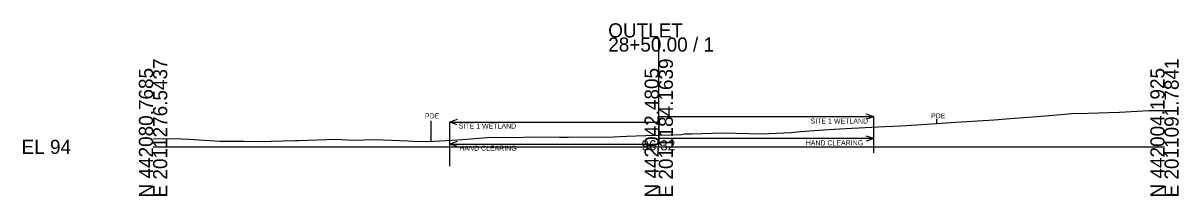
# Model space of a CAD drawing. Extents: x -26 to 1203, y -15 to 9526.
# Drawn here: x 974.3 to 1202.8, y 8490.3 to 8524.5 of the extents above; entities that cross this region are included whole.
import ezdxf

# ---------------------------------------------------------------- set-up
doc = ezdxf.new("R2010")
doc.units = 0
for name, color, linetype in [('Exist Cross Section Cell', 7, 'Continuous'), ('Exist XS Center Line Elevation Label', 7, 'Continuous'), ('Exist XS Ground Line', 7, 'Continuous'), ('Scratch_Level_0', 7, 'Continuous')]:
    doc.layers.add(name, color=color, linetype=linetype)

msp = doc.modelspace()

# ---------------------------------------------------------------- linework, layer by layer
at = {"layer": 'Exist Cross Section Cell'}
for p, q in [((1100, 8500), (1100, 8521.64)), ((1000, 8500), (1100, 8500)), ((1100, 8500), (1200, 8500))]:
    msp.add_line(p, q, dxfattribs=at)
at = {"layer": 'Exist XS Ground Line'}
msp.add_lwpolyline([(1000, 8501.57), (1002.01, 8501.66), (1005.6, 8501.56), (1007.08, 8501.51), (1013.25, 8501.1), (1017.91, 8501.13), (1020.9, 8501.04), (1028.12, 8501.23), (1028.73, 8501.26), (1036.21, 8501.55), (1039.56, 8501.36), (1043.86, 8501.43), (1050.38, 8501.17), (1051.51, 8501.14), (1054.24, 8501.07), (1059.17, 8501.32), (1061.21, 8501.49), (1066.82, 8501.95), (1072.03, 8501.86), (1074.47, 8501.99), (1080.36, 8501.93), (1082.13, 8501.95), (1082.86, 8501.97), (1089.78, 8501.94), (1093.68, 8502.1), (1097.43, 8502.22), (1100, 8502.32), (1104.51, 8502.48), (1105.08, 8502.55), (1106.48, 8502.59), (1112.74, 8502.77), (1115.33, 8502.7), (1120.39, 8502.56), (1126.16, 8502.84), (1128.04, 8503.01), (1132.6, 8503.38), (1135.7, 8503.6), (1136.98, 8503.64), (1143.35, 8503.97), (1147.81, 8504.16), (1151, 8504.38), (1158.71, 8504.89), (1166.31, 8505.37), (1169.46, 8505.64), (1173.96, 8505.97), (1180.28, 8506.49), (1181.61, 8506.57), (1184.83, 8506.66), (1191.11, 8506.87), (1196.92, 8507.2), (1200, 8507.21)], dxfattribs=at)
at = {"layer": 'Scratch_Level_0'}
for p, q in [((1142.5, 8505.95), (1141, 8506.45)), ((1055, 8501.11), (1055, 8505.12)), ((1060.15, 8505.39), (1058.65, 8504.89)), ((1060.15, 8504.39), (1058.65, 8504.89)), ((1058.65, 8504.89), (1100, 8504.89)), ((1100, 8505.95), (1100, 8500.56)), ((1142.5, 8505.95), (1100, 8505.95)), ((1142.5, 8505.95), (1141, 8505.45)), ((1142.5, 8503.92), (1142.5, 8505.95)), ((1142.5, 8498.81), (1142.5, 8503.92)), ((1155, 8504.65), (1155, 8505.51)), ((1142.5, 8501.63), (1100, 8501.63)), ((1142.5, 8501.63), (1141, 8502.13)), ((1142.5, 8501.63), (1141, 8501.13)), ((1058.65, 8496.18), (1058.65, 8501.3)), ((1060.15, 8501.06), (1058.65, 8500.56)), ((1058.65, 8500.56), (1100, 8500.56)), ((1060.15, 8500.06), (1058.65, 8500.56))]:
    msp.add_line(p, q, dxfattribs=at)
msp.add_lwpolyline([(1058.65, 8501.3), (1058.65, 8504.89)], dxfattribs=at)

# ---------------------------------------------------------------- texts
at = {"layer": 'Exist Cross Section Cell'}
for s, p in [('OUTLET', (1090, 8521.64)), ('28+50.00 / 1', (1090, 8518.84)), ('EL 94', (974, 8498.6))]:
    msp.add_text(s, height=2.8, dxfattribs=at).set_placement(p)
for s, p in [('N 442080.7685', (1000, 8490)), ('E 2011276.5437', (1002.8, 8490)), ('N 442042.4805', (1100, 8490)), ('E 2011184.1639', (1102.8, 8490)), ('N 442004.1925', (1200, 8490)), ('E 2011091.7841', (1202.8, 8490))]:
    msp.add_text(s, height=2.8, rotation=90, dxfattribs=at).set_placement(p)
at = {"layer": 'Exist XS Center Line Elevation Label'}
msp.add_text('96.32', height=2, dxfattribs=at).set_placement((1096.58, 8499.32))
at = {"layer": 'Scratch_Level_0'}
for s, p in [('PDE', (1053.76, 8505.63)), ('PDE', (1153.83, 8505.66)), ('SITE 1 WETLAND', (1060.45, 8503.62)), ('SITE 1 WETLAND', (1130.02, 8504.61)), ('HAND CLEARING', (1060.55, 8499.25)), ('HAND CLEARING', (1129.05, 8500.29))]:
    msp.add_text(s, height=1, dxfattribs=at).set_placement(p)

doc.saveas('drawing.dxf')
